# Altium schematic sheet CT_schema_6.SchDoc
size 368 x 245 mm
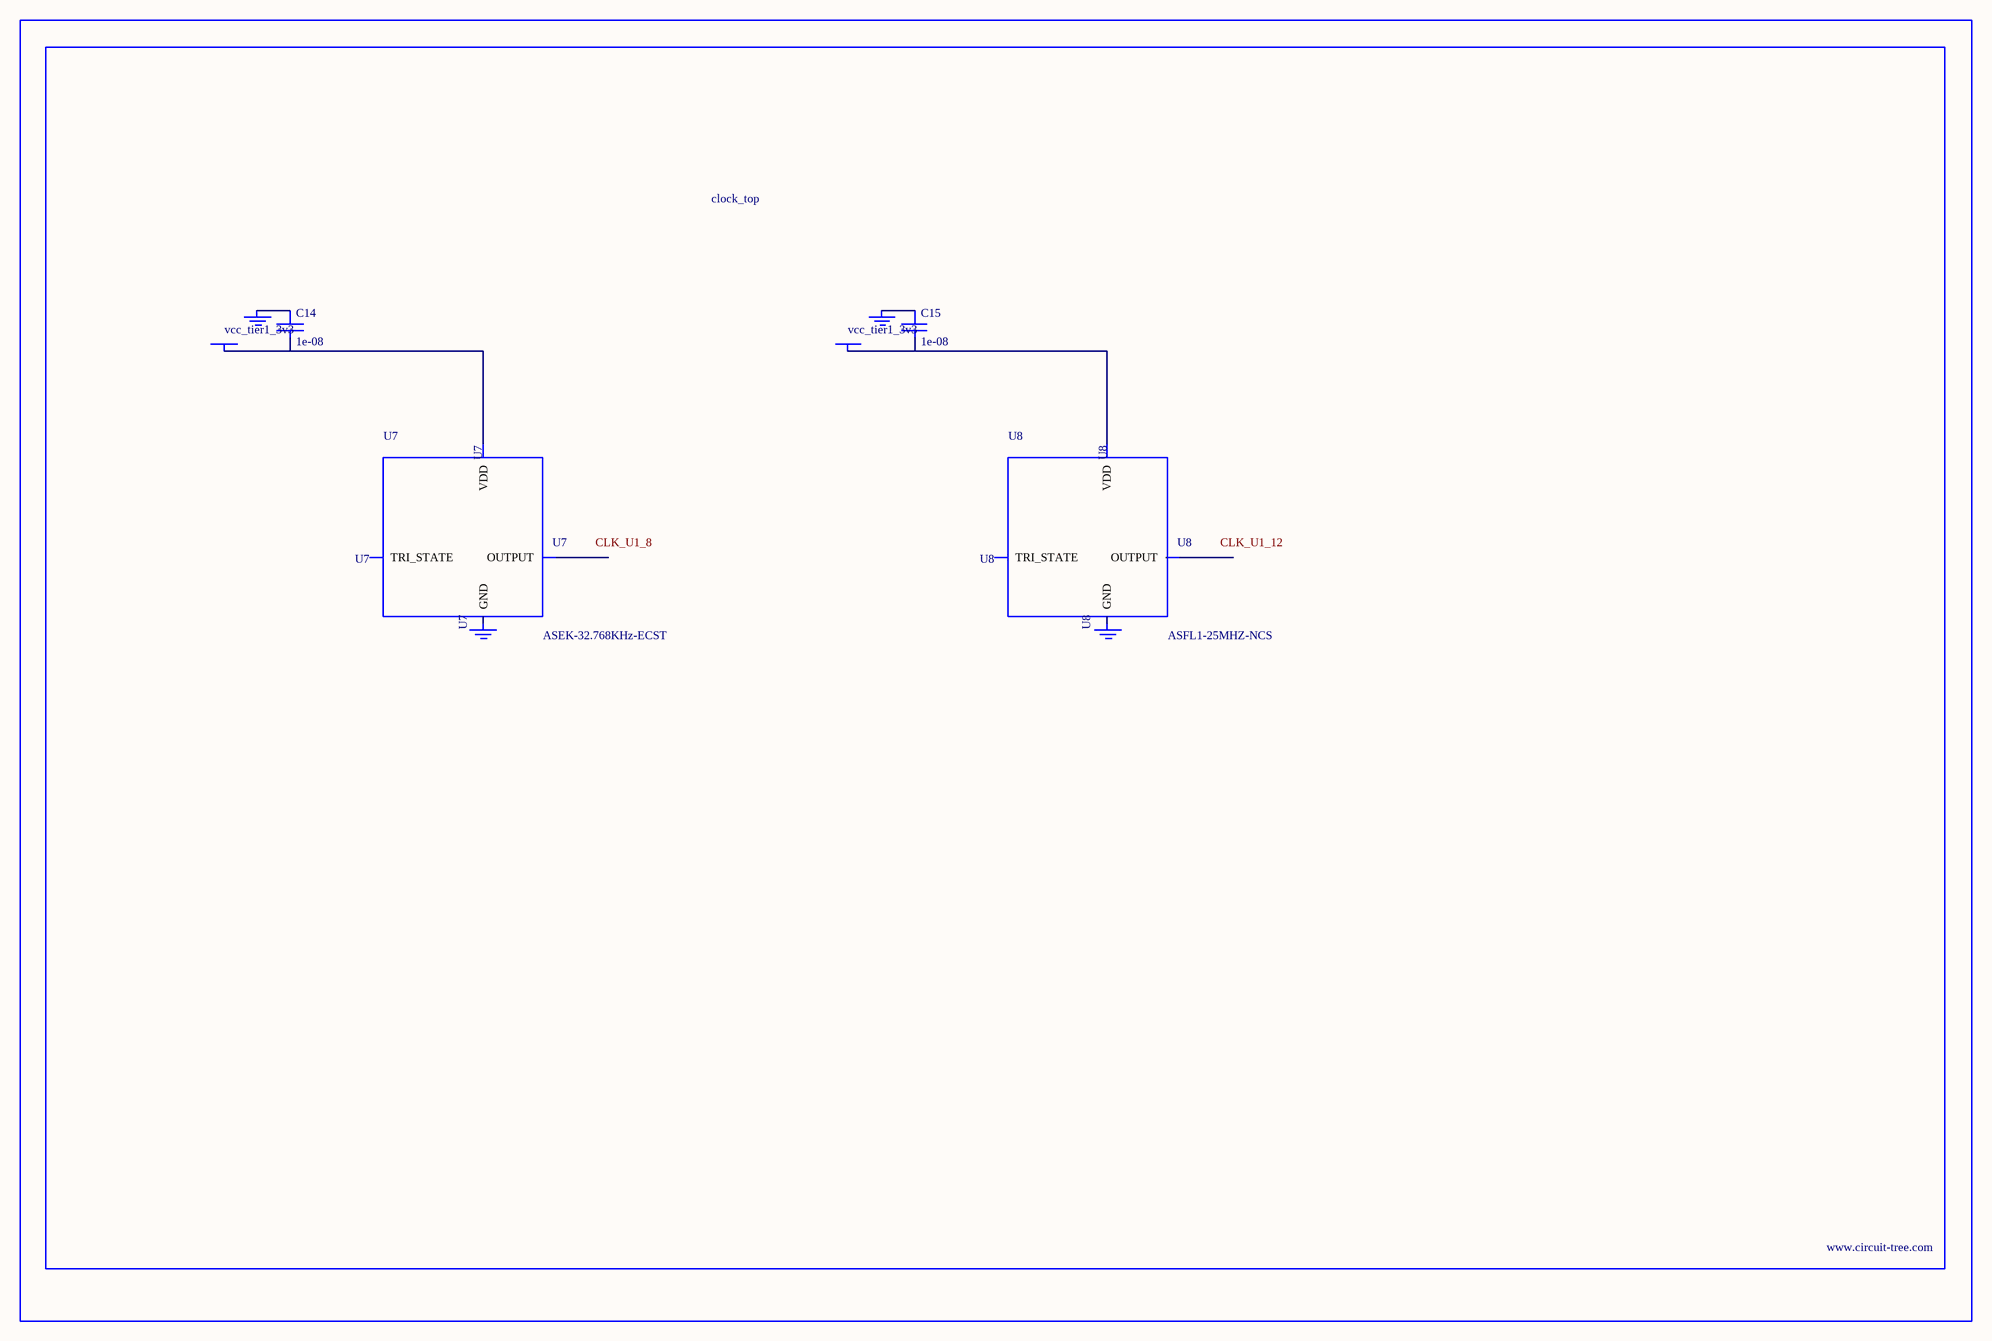
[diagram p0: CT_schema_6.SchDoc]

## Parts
BORDER5  (no value)
C14  1e-08  [C0402]
C15  1e-08  [C0402]
GND_INSTANCE_5_0  (no value)
GND_INSTANCE_5_1  (no value)
GND_INSTANCE_5_2  (no value)
GND_INSTANCE_5_3  (no value)
POWER_INSTANCE_5_0  vcc_tier1_3v3
POWER_INSTANCE_5_1  vcc_tier1_3v3
U7  ASEK-32.768KHz-ECST  [ASEK]
U8  ASFL1-25MHZ-NCS  [ASFL1]

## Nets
NetC14_1: C14.1 GND_INSTANCE_5_0.0(GND)
NetC14_2: C14.2 POWER_INSTANCE_5_0.0(PWR) U7.4(VDD)
NetC15_1: C15.1 GND_INSTANCE_5_2.0(GND)
NetC15_2: C15.2 POWER_INSTANCE_5_1.0(PWR) U8.4(VDD)

Not connected (* = marked no-connect by the designer): GND_INSTANCE_5_1 0(GND); GND_INSTANCE_5_3 0(GND); U7 1(TRI_STATE) 2(GND) 3(OUTPUT); U8 1(TRI_STATE) 2(GND) 3(OUTPUT)

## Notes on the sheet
- Labels drawn without touching a wire or pin: CLK_U1_8, CLK_U1_12

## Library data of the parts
BORDER5 = BORDER_PAGE5
C14 C15 = C0402C103K3RAC
GND_INSTANCE_5_0-GND_INSTANCE_5_3 = GND
POWER_INSTANCE_5_0 POWER_INSTANCE_5_1 = PWR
